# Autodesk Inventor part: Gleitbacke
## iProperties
Company: HERDT-Verlag
Created: 2006-01
Part Number: Gleitbacke
Material: 1.0050 St 50-2
Document SubType Name: Modeling
Designer: Eichenseer
Project: Inventor 11 - Grundkurs
Checked By: G. Lehmann
Engr Approved By: M. Grouls
Description: DIN 1017 110x22x130
Engineer: Käs
Author: P. Tropf
Subject: Inventor 10 - Grundkurs
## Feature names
1. Grundkörper [Extrusion]
2. Führungsnut [Extrusion]
3. Zentrierung [Extrusion]
4. Extrusion4
